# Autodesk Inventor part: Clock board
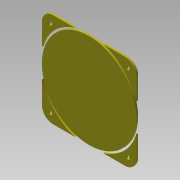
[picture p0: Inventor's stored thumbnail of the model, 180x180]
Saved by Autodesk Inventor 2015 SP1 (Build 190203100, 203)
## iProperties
Created: 2015-03
Part Number: Clock board
Material: Generic
Document SubType Name: Modeling
Designer: kazys
Density: 1 g/cm^3
Appearance: Canary
Author: kazys
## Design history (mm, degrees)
sketch "Sketch1"
  geometry: L1 (-40.64, 40.64)-(40.64, 40.64); L2 (40.64, 40.64)-(40.64, -40.64); L3 (40.64, -40.64)-(-40.64, -40.64); L4 (-40.64, -40.64)-(-40.64, 40.64); 3 further points
  constraints: 8 end point, 2 midpoint, 2 parallel, 1 horizontal, 1 horizontal alignment, 1 perpendicular, 1 vertical alignment
  dimensions: "d0" = 81.28 distance of L1.start L1.end; "d1" = 81.28 distance of L1.end L2.end
extrude "Extrusion1" new body sketch "Sketch1" distance "d2" = 1.5748; taper "d3" = 0 deg
sketch "Sketch6"
  geometry: L1 (-33.338, 33.338)-(33.338, -33.338); 4 further points
  constraints: 2 end point, 2 horizontal alignment, 2 vertical alignment, 1 coincident, 1 midpoint
  dimensions: "d31" = 66.675 distance of point (33.338, 33.338) L1.start; "d32" = 66.675 distance of L1.start point (-33.338, -33.338) (= d31)
hole "Hole1" sketch "Sketch6" at (-33.338, 33.338), (33.338, 33.338), (33.338, -33.338), (-33.338, -33.338) diameter "d33" = 3.175; stored, may be unused: countersink angle "d37" = 82 deg, drill point angle "d39" = 118 deg; dims "d34" = 19.05, "d35" = 9.525, "d36" = 6.35, "d38" = 25.4
fillet "Fillet1" dims "d4" = 9.652
sketch "Sketch2"
  geometry: C1 r 40.64 at (0, 0); C2 r 42.418 at (0, 0); 1 further point
  constraints: 2 centre point, 1 coincident
  dimensions: "d5" = 81.28 diameter of C1; "d6" = 1.778 radial gap between concentric circles of C2 C1
extrude "Extrusion5" cut sketch "Sketch2" stored distance "d29" = 1.27; taper "d30" = 0 deg
body "Solid1"
